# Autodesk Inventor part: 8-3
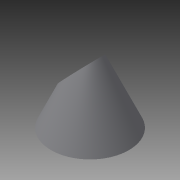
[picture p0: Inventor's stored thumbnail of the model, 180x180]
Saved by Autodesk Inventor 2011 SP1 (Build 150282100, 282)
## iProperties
Created: 2014-01
Part Number: 8-3
Document SubType Name: Modeling
Designer: Administrator
Density: 1 g/cm^3
Author: Administrator
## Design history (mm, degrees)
sketch "草图1"
  geometry: C1 r 23 at (0, 0); 1 further point
  constraints: 1 centre point, 1 coincident
  dimensions: "d0" = 46 diameter of C1
node "工作平面1"
sketch "草图2"
  geometry: 2 further points
  constraints: 1 coincident
feature "放样1" sketch "草图2" dims "d2" = 0, "d3" = 90 deg, "d4" = 0, "d5" = 90 deg
sketch "草图3"
  geometry: L1 (23, 0)-(0, 51) reference; L2 (-23, 0)-(0, 51) reference; L3 (15.562, 16.494)-(-5.553, 38.687); 1 further point
  constraints: 2 end point, 2 point on line
extrude "拉伸1" cut sketch "草图3" stored distance "d6" = 10; taper "d7" = 0 deg
node "实体1"
other parameters: "d1" = 51
